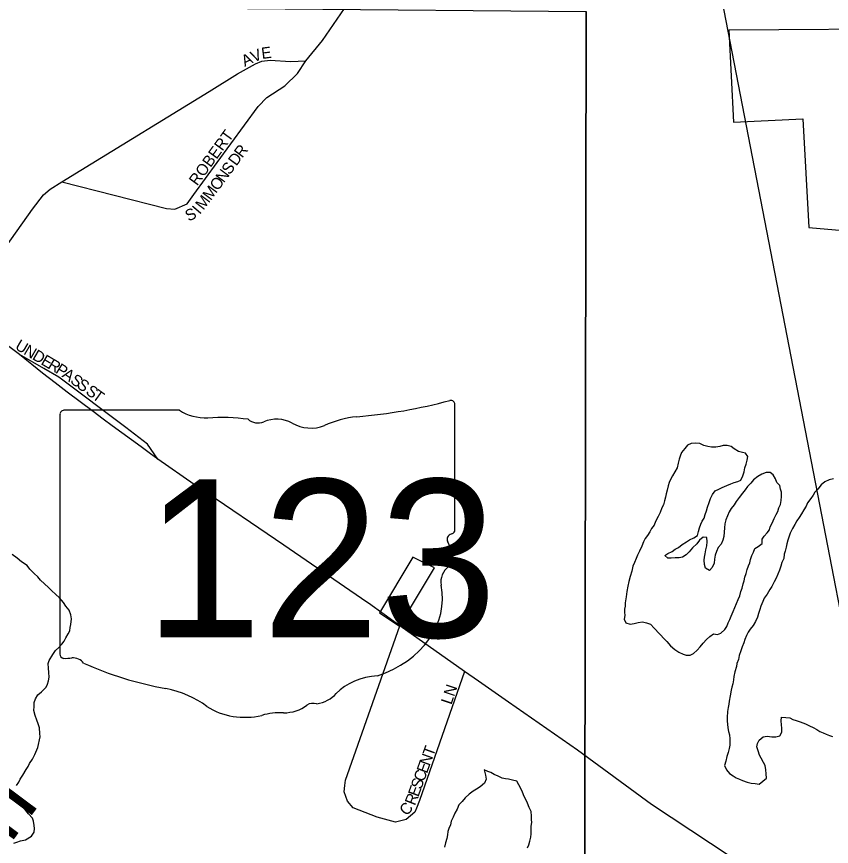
# Model space of a CAD drawing. Extents: x 0 to 1064, y 0 to 440.
# Drawn here: x 152.46 to 163.34, y 395.33 to 406.41 of the extents above; entities that cross this region are included whole.
import ezdxf

# ---------------------------------------------------------------- set-up
doc = ezdxf.new("R2010")
doc.units = 0
for name, color, linetype in [('GM_X_City_Street', 7, 'Continuous'), ('GM_X_City_Street_Text', 7, 'Continuous'), ('GM_X_Corporation', 7, 'Continuous'), ('GM_X_Minor_Lake', 7, 'Continuous'), ('GM_X_Minor_River', 7, 'Continuous'), ('GM_X_Rail_Line_Text', 7, 'Continuous'), ('GM_X_Section', 7, 'Continuous'), ('GM_X_State_Location', 7, 'Continuous'), ('GM_X_State_Route', 7, 'Continuous'), ('GM_X_State_Shield', 7, 'Continuous'), ('SH_Text', 7, 'Continuous')]:
    doc.layers.add(name, color=color, linetype=linetype)

msp = doc.modelspace()

# ---------------------------------------------------------------- linework, layer by layer
at = {"layer": 'GM_X_City_Street'}
for points in [[(153.059, 404.203), (154.457, 403.845), (154.568, 403.837), (154.732, 403.907), (154.823, 404.033), (155.135, 404.458), (155.684, 405.206), (155.798, 405.327), (156.038, 405.483), (156.207, 405.647), (156.319, 405.816), (156.541, 406.088), (156.833, 406.514)], [(151.702, 402.478), (152.669, 403.837), (152.814, 404.028), (152.905, 404.103), (153.059, 404.203), (153.314, 404.359), (155.028, 405.406), (155.405, 405.642), (155.646, 405.776), (155.732, 405.812), (155.843, 405.827), (156.113, 405.807), (156.319, 405.816)], [(154.342, 400.497), (154.203, 400.696), (153.916, 400.921), (153.018, 401.593), (152.819, 401.708), (152.496, 401.895)], [(156.841, 396.14), (156.848, 396.211), (157.574, 398.274)], [(158.439, 397.663), (157.838, 395.939), (157.798, 395.837)], [(157.798, 395.837), (157.776, 395.783), (157.658, 395.684), (157.516, 395.649), (157.273, 395.716), (156.95, 395.842), (156.875, 395.931), (156.832, 396.055), (156.841, 396.14)]]:
    msp.add_lwpolyline(points, dxfattribs=at)
at = {"layer": 'GM_X_Corporation'}
msp.add_lwpolyline([(169.972, 406.279), (161.969, 406.228), (162.033, 404.996), (162.959, 405.044), (163.036, 403.592), (165.287, 403.395)], dxfattribs=at)
msp.add_lwpolyline([(157.304, 398.444), (157.568, 398.269), (158.036, 399.048), (157.75, 399.187)], close=True, dxfattribs=at)
at = {"layer": 'GM_X_Minor_Lake'}
for points in [[(161.398, 399.219), (161.349, 399.19), (161.306, 399.178), (161.252, 399.18), (161.197, 399.175), (161.154, 399.176), (161.113, 399.213), (161.156, 399.237), (161.211, 399.266), (161.254, 399.295), (161.297, 399.319), (161.347, 399.36), (161.402, 399.395), (161.445, 399.419), (161.5, 399.448), (161.549, 399.477), (161.563, 399.532), (161.576, 399.58), (161.595, 399.628), (161.614, 399.67), (161.639, 399.712), (161.653, 399.761), (161.672, 399.809), (161.685, 399.857), (161.705, 399.918), (161.724, 399.972), (161.749, 400.026), (161.787, 400.074), (161.836, 400.097), (161.879, 400.121), (161.94, 400.144), (161.995, 400.167), (162.038, 400.184), (162.087, 400.201), (162.13, 400.219), (162.155, 400.273), (162.175, 400.327), (162.182, 400.382), (162.201, 400.43), (162.214, 400.484), (162.222, 400.533), (162.192, 400.576), (162.15, 400.589), (162.096, 400.602), (162.042, 400.634), (162, 400.665), (161.946, 400.679), (161.891, 400.68), (161.848, 400.669), (161.793, 400.658), (161.739, 400.659), (161.69, 400.666), (161.636, 400.679), (161.582, 400.705), (161.522, 400.712), (161.467, 400.707), (161.418, 400.684), (161.38, 400.642), (161.337, 400.589), (161.318, 400.54), (161.304, 400.498), (161.291, 400.444), (161.278, 400.383), (161.246, 400.329), (161.215, 400.275), (161.196, 400.233), (161.17, 400.185), (161.157, 400.142), (161.144, 400.082), (161.13, 400.034), (161.124, 399.991), (161.11, 399.943), (161.097, 399.888), (161.072, 399.846), (161.052, 399.786), (161.027, 399.732), (160.989, 399.666), (160.97, 399.618), (160.938, 399.57), (160.913, 399.528), (160.882, 399.48), (160.851, 399.438), (160.831, 399.396), (160.806, 399.335), (160.774, 399.269), (160.749, 399.215), (160.729, 399.173), (160.71, 399.118), (160.685, 399.07), (160.671, 399.004), (160.651, 398.931), (160.632, 398.865), (160.618, 398.804), (160.605, 398.732), (160.597, 398.659), (160.583, 398.58), (160.582, 398.537), (160.575, 398.495), (160.574, 398.453), (160.579, 398.41), (160.572, 398.361)], [(161.303, 397.92), (161.357, 397.894), (161.399, 397.881), (161.454, 397.88), (161.497, 397.903), (161.546, 397.945), (161.584, 397.993), (161.627, 398.041), (161.671, 398.088), (161.714, 398.13), (161.764, 398.165), (161.818, 398.158), (161.861, 398.175), (161.917, 398.223), (161.942, 398.265), (161.961, 398.313), (161.98, 398.355), (161.999, 398.403), (162.025, 398.464), (162.05, 398.518), (162.07, 398.572), (162.095, 398.626), (162.114, 398.674), (162.128, 398.729), (162.147, 398.777), (162.16, 398.832), (162.173, 398.874), (162.181, 398.922), (162.2, 398.971), (162.213, 399.025), (162.232, 399.073), (162.251, 399.115), (162.258, 399.158), (162.278, 399.212), (162.297, 399.254), (162.316, 399.303), (162.359, 399.332), (162.415, 399.373), (162.416, 399.428), (162.441, 399.47), (162.479, 399.512), (162.51, 399.554), (162.523, 399.596), (162.548, 399.644), (162.574, 399.704), (162.599, 399.759), (162.624, 399.801), (162.638, 399.849), (162.657, 399.891), (162.67, 399.945), (162.671, 400), (162.672, 400.055), (162.661, 400.098), (162.65, 400.147), (162.608, 400.184), (162.591, 400.233), (162.562, 400.288), (162.52, 400.32), (162.466, 400.321), (162.411, 400.298), (162.355, 400.268), (162.3, 400.221), (162.262, 400.179), (162.219, 400.132), (162.188, 400.09), (162.15, 400.042), (162.107, 399.988), (162.069, 399.934), (162.038, 399.886), (162, 399.838), (161.975, 399.796), (161.95, 399.742), (161.93, 399.688), (161.917, 399.633), (161.91, 399.579), (161.908, 399.524), (161.901, 399.464), (161.888, 399.415), (161.868, 399.361), (161.825, 399.319), (161.806, 399.265), (161.786, 399.217), (161.779, 399.162), (161.772, 399.108), (161.746, 399.053), (161.709, 399.012), (161.655, 399.043), (161.644, 399.092), (161.639, 399.147), (161.646, 399.189), (161.653, 399.232), (161.66, 399.286), (161.674, 399.341), (161.681, 399.395), (161.676, 399.45), (161.628, 399.457), (161.578, 399.416), (161.541, 399.368), (161.485, 399.314), (161.441, 399.261), (161.398, 399.219)], [(163.368, 400.234), (163.307, 400.224), (163.252, 400.194), (163.203, 400.153), (163.159, 400.099), (163.116, 400.057), (163.096, 400.015), (163.065, 399.973), (163.021, 399.914), (163.002, 399.871), (162.971, 399.823), (162.939, 399.769), (162.908, 399.721), (162.877, 399.673), (162.851, 399.625), (162.82, 399.571), (162.788, 399.511), (162.775, 399.469), (162.756, 399.415), (162.742, 399.366), (162.735, 399.324), (162.722, 399.269), (162.709, 399.227), (162.702, 399.173), (162.676, 399.118), (162.663, 399.07), (162.644, 399.016), (162.624, 398.961), (162.599, 398.907), (162.574, 398.859), (162.542, 398.799), (162.517, 398.757), (162.479, 398.697), (162.442, 398.643), (162.422, 398.595), (162.397, 398.535), (162.384, 398.492), (162.364, 398.438), (162.351, 398.39), (162.325, 398.329), (162.294, 398.275), (162.256, 398.228), (162.225, 398.186), (162.206, 398.143), (162.181, 398.089), (162.168, 398.047), (162.148, 397.993), (162.129, 397.938), (162.109, 397.878), (162.096, 397.824), (162.077, 397.769), (162.07, 397.727), (162.05, 397.66), (162.036, 397.594), (162.029, 397.551), (162.022, 397.497), (162.009, 397.455), (162.002, 397.412), (161.988, 397.339), (161.975, 397.267), (161.968, 397.224), (161.961, 397.182), (161.953, 397.127), (161.946, 397.048), (161.945, 397), (161.95, 396.957), (161.955, 396.908), (161.966, 396.859), (161.977, 396.817), (161.982, 396.762), (161.981, 396.719), (161.98, 396.677), (161.973, 396.634), (161.96, 396.58), (161.94, 396.526), (161.927, 396.465), (161.913, 396.405), (161.937, 396.349), (161.978, 396.3), (162.026, 396.268), (162.068, 396.243), (162.11, 396.224), (162.152, 396.205), (162.212, 396.185), (162.266, 396.172), (162.321, 396.165), (162.375, 396.157)], [(160.572, 398.361), (160.595, 398.312), (160.65, 398.293), (160.705, 398.304), (160.759, 398.315), (160.814, 398.326), (160.869, 398.312), (160.923, 398.293), (160.971, 398.243)], [(160.971, 398.243), (161.116, 398.091)], [(161.116, 398.091), (161.142, 398.063), (161.19, 398.007), (161.249, 397.957), (161.303, 397.92)], [(162.375, 396.157), (162.474, 396.24), (162.469, 396.295), (162.465, 396.35), (162.454, 396.405), (162.43, 396.448), (162.401, 396.503), (162.378, 396.546), (162.361, 396.602), (162.344, 396.657), (162.351, 396.699), (162.376, 396.747), (162.426, 396.789), (162.48, 396.8), (162.541, 396.792), (162.595, 396.791), (162.65, 396.802), (162.676, 396.85), (162.677, 396.905), (162.672, 396.948), (162.667, 397.002), (162.674, 397.051), (162.729, 397.05), (162.783, 397.042), (162.825, 397.023), (162.867, 397.01), (162.921, 396.991), (162.994, 396.965), (163.048, 396.939), (163.096, 396.914), (163.144, 396.889), (163.186, 396.863), (163.228, 396.844), (163.27, 396.825), (163.312, 396.806), (163.354, 396.793)], [(158.7, 396.35), (158.719, 396.279), (158.729, 396.224), (158.704, 396.17), (158.648, 396.123), (158.599, 396.093), (158.556, 396.064), (158.501, 396.023), (158.445, 395.975), (158.407, 395.927), (158.364, 395.88), (158.339, 395.825), (158.307, 395.771), (158.288, 395.717), (158.262, 395.663), (158.249, 395.614), (158.23, 395.566), (158.217, 395.524), (158.21, 395.482), (158.203, 395.433), (158.183, 395.373), (158.17, 395.318)], [(159.28, 395.306), (159.299, 395.348), (159.312, 395.397), (159.326, 395.451), (159.327, 395.494), (159.328, 395.548), (159.329, 395.597), (159.336, 395.646), (159.331, 395.688), (159.332, 395.731), (159.327, 395.792), (159.304, 395.847), (159.281, 395.902), (159.258, 395.951), (159.234, 395.994), (159.211, 396.05), (159.194, 396.093), (159.165, 396.148), (159.136, 396.197), (159.081, 396.211), (159.027, 396.224), (158.985, 396.231), (158.942, 396.238), (158.888, 396.263), (158.834, 396.289), (158.792, 396.314), (158.75, 396.327), (158.7, 396.35)]]:
    msp.add_lwpolyline(points, dxfattribs=at)
at = {"layer": 'GM_X_Minor_River'}
for points in [[(152.453, 396.142), (152.484, 396.184), (152.503, 396.226), (152.54, 396.28), (152.585, 396.352), (152.61, 396.394), (152.629, 396.436), (152.666, 396.49), (152.698, 396.556), (152.737, 396.647), (152.75, 396.689), (152.763, 396.749), (152.77, 396.792), (152.765, 396.834), (152.76, 396.908), (152.743, 396.963), (152.726, 397.012), (152.703, 397.073), (152.687, 397.14), (152.688, 397.195), (152.689, 397.25), (152.708, 397.298), (152.74, 397.352), (152.789, 397.393), (152.851, 397.453), (152.87, 397.495), (152.883, 397.537), (152.89, 397.586), (152.886, 397.647), (152.881, 397.708), (152.876, 397.769), (152.889, 397.811), (152.94, 397.889), (152.977, 397.943), (153.021, 397.984), (153.058, 398.026), (153.089, 398.068), (153.114, 398.11), (153.146, 398.164), (153.165, 398.206), (153.172, 398.249), (153.179, 398.291), (153.187, 398.364), (153.182, 398.419), (153.159, 398.48), (153.111, 398.536), (153.082, 398.585), (153.029, 398.647), (152.975, 398.697), (152.928, 398.74), (152.88, 398.784), (152.827, 398.834), (152.773, 398.884), (152.738, 398.927), (152.69, 398.971), (152.63, 399.027), (152.595, 399.076), (152.523, 399.126), (152.464, 399.176), (152.398, 399.226)], [(152.418, 395.37), (152.46, 395.382), (152.509, 395.399), (152.576, 395.416), (152.656, 395.462), (152.688, 395.517), (152.695, 395.565), (152.69, 395.608), (152.679, 395.663), (152.668, 395.705), (152.614, 395.761), (152.579, 395.805), (152.537, 395.86), (152.49, 395.922), (152.467, 395.965), (152.45, 396.014)]]:
    msp.add_lwpolyline(points, dxfattribs=at)
at = {"layer": 'GM_X_Section'}
msp.add_lwpolyline([(143.975, 406.617), (160.061, 406.476), (160.036, 390.151), (143.725, 390.273)], close=True, dxfattribs=at)
msp.add_lwpolyline([(163.563, 392.286), (163.292, 391.164), (163.213, 390.541), (163.173, 390.366), (162.733, 390.163), (161.962, 390.118), (161.278, 390.144), (160.036, 390.151), (160.061, 406.476)], dxfattribs=at)
at = {"layer": 'GM_X_State_Route'}
for points in [[(152.97, 401.517), (152.803, 401.644), (152.496, 401.895), (152.261, 402.068), (151.83, 402.384)], [(153.478, 401.134), (153.133, 401.392), (152.97, 401.517)], [(153.734, 400.944), (153.612, 401.034), (153.478, 401.134)], [(154.118, 400.661), (153.734, 400.944)], [(154.246, 400.567), (154.118, 400.661)], [(154.9, 400.113), (154.828, 400.161), (154.342, 400.497), (154.246, 400.567)], [(157.135, 398.588), (156.025, 399.349), (154.9, 400.113)], [(162.089, 395.122), (161.985, 395.194), (160.936, 395.888), (159.949, 396.614), (159.026, 397.252), (158.623, 397.532), (158.439, 397.663), (157.574, 398.274), (157.157, 398.573), (157.135, 398.588)]]:
    msp.add_lwpolyline(points, dxfattribs=at)
at = {"layer": 'GM_X_State_Shield'}
for p, q in [((154.632, 401.15), (153.087, 401.15)), ((158.309, 399.554), (158.309, 401.229)), ((153.035, 401.095), (153.035, 397.893)), ((158.308, 399.555), (158.309, 399.554))]:
    msp.add_line(p, q, dxfattribs=at)
for centre, major_axis, start_param, end_param in [((156.43, 405.515), (5.592, 0), 4.814394, 5.042369), ((158.25, 401.236), (0.0587, 0), 6.141152, 7.989035), ((153.096, 401.102), (0.0611, 0), 1.712693, 3.28349), ((154.999, 401.522), (0.593, 0), 4.042523, 4.731795), ((155.196, 399.352), (2.127, 0), 1.404758, 1.657858), ((155.679, 401.118), (0.171, 0), 3.836095, 5.185415), ((155.93, 400.748), (0.355, 0), 0.950623, 2.079405), ((157.144, 400.172), (1.125, 0), 1.699011, 2.107814), ((156.389, 401.256), (0.428, 0), 4.081561, 5.145723), ((158.295, 399.431), (0.0909, 0), 1.883978, 3.671073), ((158.246, 399.548), (0.0628, 0), 5.05454, 6.418171), ((157.717, 399.22), (0.545, 0), 5.934695, 6.695948), ((158.519, 398.853), (0.397, 0), 2.387724, 3.262537), ((156.744, 398.64), (1.399, 0), 5.101752, 6.440018), ((153.096, 397.886), (0.0616, 0), 3.00124, 4.508301), ((153.106, 398.214), (0.47, 0), 4.665946, 4.897461), ((153.202, 397.708), (0.17, 0), 0.519207, 1.627899), ((155.343, 400.585), (4.038, 0), 4.195997, 4.488961), ((157.333, 396.994), (0.766, 0), 1.647645, 2.488434), ((154.139, 396.454), (1.264, 0), 0.823519, 1.323587), ((156.363, 397.583), (0.452, 0), 4.937069, 5.64225), ((155.506, 397.692), (0.802, 0), 4.026481, 4.996735), ((156.028, 397.453), (0.427, 0), 4.691044, 5.507374), ((156.414, 397.142), (0.12, 0), 1.147584, 2.315152), ((155.969, 396.585), (0.659, 0), 1.495662, 1.94098)]:
    msp.add_ellipse(centre, major_axis=major_axis, ratio=0.8, start_param=start_param, end_param=end_param, dxfattribs=at)
at = {"layer": 'SH_Text'}
msp.add_lwpolyline([(160.517, 413.642), (164.374, 393.73), (164.93, 413.642)], close=True, dxfattribs=at)

# ---------------------------------------------------------------- texts
at = {"layer": 'GM_X_City_Street_Text'}
for s, height, rotation, p in [('A', 0.152, 25.734, (155.503, 405.735)), ('V', 0.152, 22.946, (155.621, 405.792)), ('E', 0.152, 7.4538, (155.734, 405.841)), ('ROBERT', 0.1515, 53.9697, (154.867, 404.139)), ('R', 0.152, 53.4353, (155.469, 404.511)), ('D', 0.152, 53.436, (155.39, 404.404)), ('S', 0.152, 53.4448, (155.302, 404.286)), ('N', 0.152, 53.436, (155.223, 404.179)), ('O', 0.152, 53.4585, (155.144, 404.072)), ('M', 0.152, 53.32, (155.048, 403.943)), ('M', 0.152, 52.8473, (154.95, 403.815)), ('S', 0.152, 26.0884, (154.752, 403.668)), ('I', 0.152, 49.6425, (154.901, 403.757)), ('U', 0.152, 329.5611, (152.424, 401.974)), ('N', 0.152, 329.5626, (152.539, 401.906)), ('D', 0.152, 329.5626, (152.654, 401.839)), ('E', 0.152, 329.5644, (152.769, 401.771)), ('R', 0.152, 329.5443, (152.861, 401.717)), ('P', 0.152, 328.0381, (152.964, 401.657)), ('A', 0.152, 324.9399, (153.052, 401.602)), ('S', 0.152, 324.3543, (153.161, 401.525)), ('S', 0.152, 324.294, (153.248, 401.463)), ('S', 0.152, 324.294, (153.367, 401.378)), ('T', 0.152, 324.3503, (153.454, 401.315)), ('LN', 0.1515, 71.5687, (158.263, 397.212)), ('T', 0.152, 70.0134, (158.018, 396.518)), ('N', 0.152, 70.0049, (157.972, 396.393)), ('E', 0.152, 70.0005, (157.936, 396.292)), ('C', 0.152, 70.0293, (157.895, 396.18)), ('S', 0.152, 70.0466, (157.858, 396.079)), ('E', 0.152, 69.8228, (157.821, 395.979)), ('R', 0.152, 68.4774, (157.776, 395.863)), ('C', 0.152, 48.5399, (157.666, 395.725))]:
    msp.add_text(s, height=height, rotation=rotation, dxfattribs=at).set_placement(p)
at = {"layer": 'GM_X_Rail_Line_Text'}
msp.add_text('Corporation', height=0.90606, rotation=53.2781, dxfattribs=at).set_placement((148.985, 390.819))
at = {"layer": 'GM_X_State_Location'}
for s in ['s', 'r']:
    msp.add_text(s, height=0.00303, dxfattribs=at).set_placement((155.613, 399.281))
msp.add_text('123', height=0.00303, rotation=0, dxfattribs=at).set_placement((154.543, 399.061))
at = {"layer": 'GM_X_State_Shield'}
msp.add_text('123', height=2.1094, dxfattribs=at).set_placement((154.166, 398.119))

doc.saveas('drawing.dxf')
